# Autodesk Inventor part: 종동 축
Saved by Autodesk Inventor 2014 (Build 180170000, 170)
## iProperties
Created: 2026-10
Part Number: 종동 축
Material: 일반
Document SubType Name: Modeling
Designer: dg
Density: 1 g/cm^3
Appearance: 기본값
Author: dg
Author: jhkim
Creation Date: 2026-09-29
Sending System: Autodesk Inventor 2027
Preprocessor: ST-DEVELOPER v20.1
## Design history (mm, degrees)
node "종동 축1"
node "솔리드1"
node "기준1"
